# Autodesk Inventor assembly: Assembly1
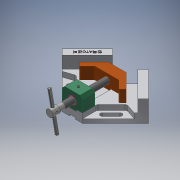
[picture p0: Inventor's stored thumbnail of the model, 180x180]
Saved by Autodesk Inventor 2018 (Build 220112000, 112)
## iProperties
Created: 2019-04
Part Number: Assembly1
Document SubType Name: Assembly
Designer: Administrator
Author: Administrator
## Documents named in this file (10)
- C:\Users\expoc\Desktop\490408V1009\Assembly1.iam
- C:\Users\expoc\Desktop\490408V1009\본체.ipt
- C:\Users\expoc\Desktop\490408V1009\리드스크류.ipt
- C:\Users\expoc\Desktop\490408V1009\서포트.ipt
- C:\Users\expoc\Desktop\490408V1009\조.ipt
- C:\Users\expoc\Desktop\490408V1009\부시.ipt
- C:\Users\expoc\Desktop\490408V1009\핸들.ipt
- C:\Users\expoc\Desktop\490408V1009\멈춤나사 M4x10.ipt
- C:\Users\expoc\Desktop\490408V1009\평행 핀 2.5x24.ipt
- C:\Users\expoc\Desktop\490408V1009\볼트 M4x16.ipt
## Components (1 placed, 1 different names)
1. 핸들:1 — Mate:12, Mate:13
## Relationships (2: Mate 2)
- Mate:12: 핸들:1
- Mate:13: 핸들:1
